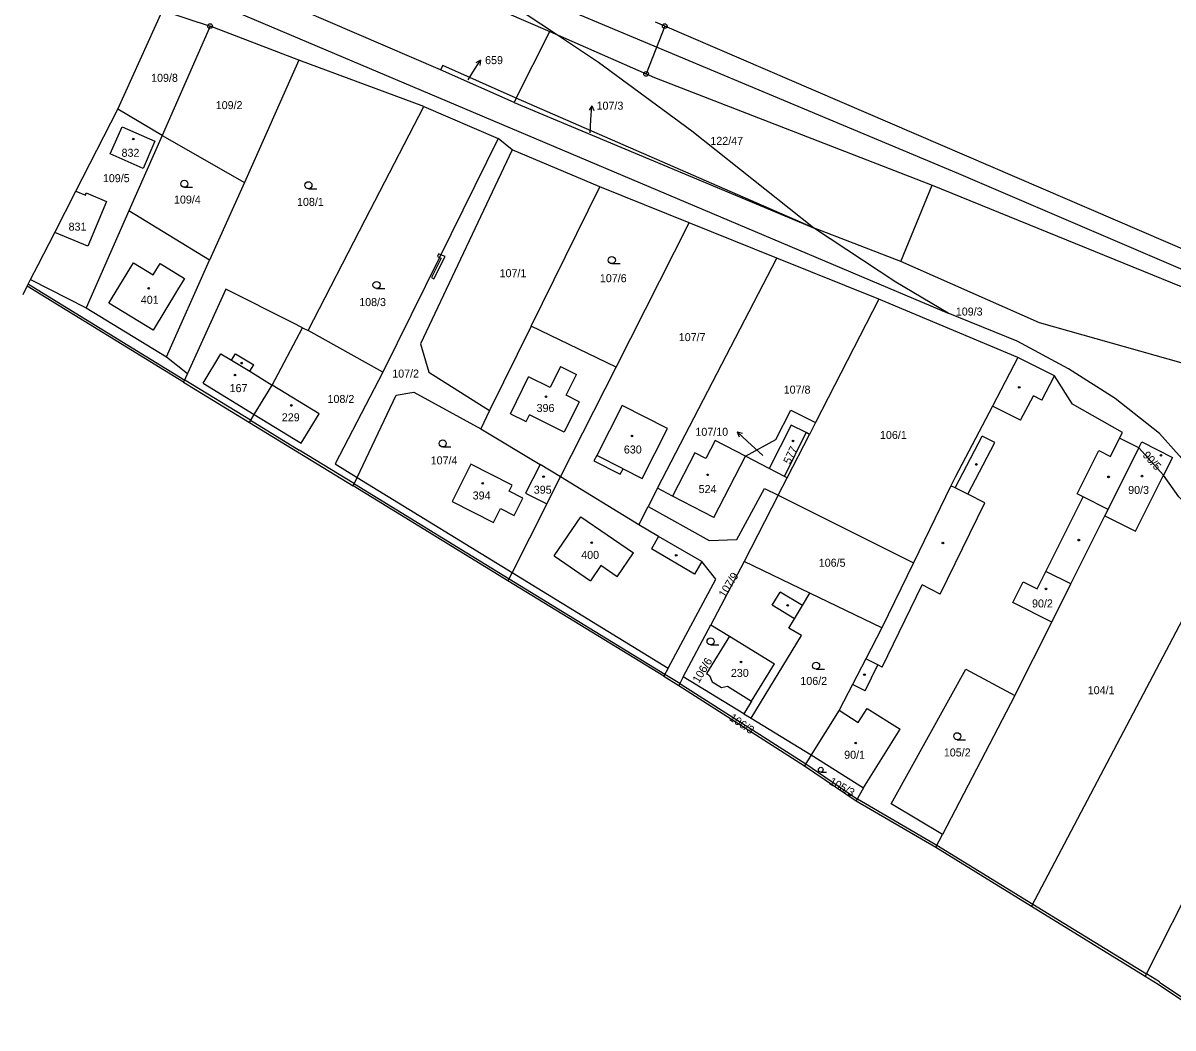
# Model space of a CAD drawing. Extents: x -783948 to -781889, y -1005870 to -1004430.
# Drawn here: x -783947.8 to -783703.5, y -1004871.2 to -1004657.7 of the extents above; entities that cross this region are included whole.
import ezdxf

# ---------------------------------------------------------------- set-up
doc = ezdxf.new("R2010")
doc.units = 0
for name, color, linetype in [('Vrstva 1', 7, 'Continuous'), ('Vrstva 13', 7, 'Continuous'), ('Vrstva 2', 7, 'Continuous'), ('Vrstva 3', 7, 'Continuous'), ('Vrstva 4', 7, 'Continuous'), ('Vrstva 5', 7, 'Continuous'), ('Vrstva 6', 7, 'Continuous'), ('Vrstva 7', 7, 'Continuous'), ('Vrstva 8', 7, 'Continuous')]:
    doc.layers.add(name, color=color, linetype=linetype)

msp = doc.modelspace()

# ---------------------------------------------------------------- linework, layer by layer
at = {"layer": 'Vrstva 1'}
for p, q in [((-783859.07, -1004667.69), (-783913.24, -1004644.21)), ((-783927.63, -1004676), (-783918.15, -1004655.06)), ((-783918.15, -1004655.06), (-783908.05, -1004658.37)), ((-783908.05, -1004658.37), (-783918.22, -1004681.57)), ((-783889.23, -1004665.59), (-783908.05, -1004658.37)), ((-783843.03, -1004673.66), (-783835.87, -1004659.49)), ((-783835.87, -1004659.49), (-783815.43, -1004668.52)), ((-783811.46, -1004658.38), (-783815.43, -1004668.52)), ((-783811.46, -1004658.38), (-783813.39, -1004657.55)), ((-783889.23, -1004665.59), (-783900.76, -1004691.57)), ((-783862.67, -1004675.47), (-783889.23, -1004665.59)), ((-783843.48, -1004674.57), (-783859.07, -1004667.69)), ((-783843.03, -1004673.66), (-783843.48, -1004674.57)), ((-783779.82, -1004701.19), (-783843.03, -1004673.66)), ((-783936.56, -1004693.41), (-783927.63, -1004676)), ((-783918.22, -1004681.57), (-783927.63, -1004676)), ((-783862.67, -1004675.47), (-783846.85, -1004682.27)), ((-783843.48, -1004674.57), (-783779.82, -1004701.19)), ((-783918.22, -1004681.57), (-783925.3, -1004697.6)), ((-783918.22, -1004681.57), (-783900.76, -1004691.57)), ((-783843.84, -1004684.65), (-783846.85, -1004682.27)), ((-783825.24, -1004692.52), (-783843.84, -1004684.65)), ((-783941.05, -1004702.18), (-783936.56, -1004693.41)), ((-783936.56, -1004693.41), (-783934.55, -1004694.26)), ((-783900.76, -1004691.57), (-783908.15, -1004708.1)), ((-783839.81, -1004722.07), (-783825.24, -1004692.52)), ((-783806.24, -1004700.16), (-783825.24, -1004692.52)), ((-783761.32, -1004708.36), (-783754.62, -1004692.14)), ((-783925.3, -1004697.6), (-783934.4, -1004718.22)), ((-783908.15, -1004708.1), (-783925.3, -1004697.6)), ((-783821.76, -1004730.78), (-783806.24, -1004700.16)), ((-783787.62, -1004707.64), (-783806.24, -1004700.16)), ((-783761.32, -1004708.36), (-783779.82, -1004701.19)), ((-783944.6, -1004709.09), (-783941.05, -1004702.18)), ((-783934.05, -1004705.1), (-783941.05, -1004702.18)), ((-783917.33, -1004728.64), (-783908.15, -1004708.1)), ((-783812.98, -1004756.53), (-783787.62, -1004707.64)), ((-783766, -1004716.39), (-783787.62, -1004707.64)), ((-783946.18, -1004712.18), (-783944.6, -1004709.09)), ((-783946.92, -1004713.62), (-783946.18, -1004712.18)), ((-783946.18, -1004712.18), (-783934.4, -1004718.22)), ((-783947.8, -1004715.34), (-783946.92, -1004713.62)), ((-783934.4, -1004718.22), (-783917.33, -1004728.64)), ((-783766, -1004716.39), (-783779.43, -1004742.59)), ((-783736.41, -1004728.73), (-783766, -1004716.39)), ((-783894.86, -1004734.6), (-783888.4, -1004722.45)), ((-783888.4, -1004722.45), (-783890.48, -1004721.4)), ((-783888.4, -1004722.45), (-783887.23, -1004723.03)), ((-783871.33, -1004731.87), (-783887.23, -1004723.03)), ((-783839.81, -1004722.07), (-783848.66, -1004740.03)), ((-783821.76, -1004730.78), (-783839.81, -1004722.07)), ((-783917.33, -1004728.64), (-783912.85, -1004732.15)), ((-783833.58, -1004754.1), (-783821.76, -1004730.78)), ((-783898.68, -1004740.83), (-783894.86, -1004734.6)), ((-783848.66, -1004740.03), (-783850.56, -1004743.9)), ((-783899.71, -1004742.52), (-783898.68, -1004740.83)), ((-783779.43, -1004742.59), (-783780.7, -1004745.07)), ((-783850.56, -1004743.9), (-783837.92, -1004751.49)), ((-783785.44, -1004754.31), (-783780.7, -1004745.07)), ((-783710.73, -1004747.93), (-783714.81, -1004745.89)), ((-783789.3, -1004752.31), (-783794.29, -1004749.72)), ((-783705.48, -1004753.77), (-783710.73, -1004747.93)), ((-783833.58, -1004754.1), (-783837.92, -1004751.49)), ((-783876.79, -1004754.24), (-783843.87, -1004774.4)), ((-783836.5, -1004759.86), (-783833.58, -1004754.1)), ((-783816.99, -1004764.26), (-783833.58, -1004754.1)), ((-783787.34, -1004758.01), (-783785.44, -1004754.31)), ((-783812.98, -1004756.53), (-783814.98, -1004760.38)), ((-783836.5, -1004759.86), (-783843.87, -1004774.4)), ((-783787.34, -1004758.01), (-783794.56, -1004772.1)), ((-783787.34, -1004758.01), (-783758.6, -1004772.33)), ((-783816.99, -1004764.26), (-783814.98, -1004760.38)), ((-783692.95, -1004768.16), (-783733.53, -1004845.25)), ((-783843.87, -1004774.4), (-783810.74, -1004794.7)), ((-783794.56, -1004772.1), (-783801.67, -1004785.52)), ((-783780.6, -1004778.83), (-783794.56, -1004772.1)), ((-783758.6, -1004772.33), (-783765.35, -1004786.19)), ((-783765.35, -1004786.19), (-783780.6, -1004778.83)), ((-783807.52, -1004796.54), (-783801.67, -1004785.52)), ((-783801.67, -1004785.52), (-783797.7, -1004787.95)), ((-783737.04, -1004800.55), (-783729.23, -1004784.93)), ((-783674.46, -1004791.02), (-783709.36, -1004860.11)), ((-783807.52, -1004796.54), (-783808.49, -1004798.38)), ((-783808.49, -1004798.38), (-783781.77, -1004815.48)), ((-783794.63, -1004804.42), (-783807.52, -1004796.54)), ((-783737.04, -1004800.55), (-783752.47, -1004830.07)), ((-783794.63, -1004804.42), (-783793.09, -1004805.36)), ((-783793.09, -1004805.36), (-783780.33, -1004813.16)), ((-783780.33, -1004813.16), (-783781.77, -1004815.48)), ((-783781.77, -1004815.48), (-783770.77, -1004822.93)), ((-783770.77, -1004822.93), (-783753.87, -1004832.75)), ((-783753.87, -1004832.75), (-783752.47, -1004830.07)), ((-783753.87, -1004832.75), (-783733.53, -1004845.25)), ((-783733.53, -1004845.25), (-783709.36, -1004860.11))]:
    msp.add_line(p, q, dxfattribs=at)
for points in [[(-783909.2, -1004634.42), (-783879.66, -1004642.5), (-783845.57, -1004655.35), (-783835.87, -1004659.49)], [(-783641.32, -1004731.39), (-783646.42, -1004729.36), (-783811.46, -1004658.38)], [(-783843.03, -1004673.66), (-783858.6, -1004666.75), (-783859.07, -1004667.69)], [(-783815.43, -1004668.52), (-783813.64, -1004669.31), (-783754.62, -1004692.14)], [(-783887.23, -1004723.03), (-783875.09, -1004699.51), (-783862.67, -1004675.47)], [(-783926.71, -1004679.77), (-783919.76, -1004682.83), (-783922.3, -1004688.59), (-783929.26, -1004685.51), (-783926.71, -1004679.77)], [(-783846.85, -1004682.27), (-783859.31, -1004707.52), (-783871.33, -1004731.87)], [(-783843.84, -1004684.65), (-783863.35, -1004725.85), (-783861.61, -1004731.84), (-783848.66, -1004740.03)], [(-783934.55, -1004694.26), (-783934.36, -1004693.8), (-783930.05, -1004695.61), (-783934.05, -1004705.1)], [(-783754.62, -1004692.14), (-783685.35, -1004720.33), (-783646.14, -1004738.05)], [(-783651.32, -1004749.59), (-783689.22, -1004733.41), (-783731.86, -1004721.38), (-783761.32, -1004708.36)], [(-783890.48, -1004721.4), (-783904.68, -1004714.23), (-783912.85, -1004732.15)], [(-783736.41, -1004728.73), (-783741.83, -1004739.06), (-783749.77, -1004754.2), (-783750.65, -1004756), (-783758.6, -1004772.33)], [(-783714.81, -1004745.89), (-783714.19, -1004744.65), (-783724.85, -1004738.66), (-783728.62, -1004732.62), (-783736.41, -1004728.73)], [(-783912.85, -1004732.15), (-783913.68, -1004733.97), (-783899.71, -1004742.52)], [(-783871.33, -1004731.87), (-783881.49, -1004751.36), (-783876.79, -1004754.24)], [(-783898.68, -1004740.83), (-783888.68, -1004746.96), (-783884.86, -1004740.73), (-783894.86, -1004734.6)], [(-783876.79, -1004754.24), (-783868.52, -1004736.77), (-783864.75, -1004736.11), (-783850.56, -1004743.9)], [(-783826.49, -1004750.71), (-783820.9, -1004753.54), (-783820.31, -1004752.37), (-783816.22, -1004754.45), (-783810.84, -1004743.84), (-783820.52, -1004738.93), (-783825.9, -1004749.54), (-783826.49, -1004750.71)], [(-783794.29, -1004749.72), (-783787.87, -1004746.14), (-783784.67, -1004739.9), (-783779.43, -1004742.59)], [(-783899.71, -1004742.52), (-783877.64, -1004756.04), (-783876.79, -1004754.24)], [(-783780.7, -1004745.07), (-783781.4, -1004744.71), (-783784.57, -1004743.09), (-783789.3, -1004752.31)], [(-783794.29, -1004749.72), (-783800.75, -1004746.37), (-783802.73, -1004750.19), (-783805.05, -1004748.99), (-783809.81, -1004758.17), (-783812.98, -1004756.53)], [(-783729.23, -1004784.93), (-783737.5, -1004780.79), (-783735.29, -1004776.37), (-783732.34, -1004777.85), (-783730.5, -1004774.17), (-783722.59, -1004758.35), (-783723.85, -1004757.72), (-783719.26, -1004748.53), (-783716.75, -1004749.78), (-783714.81, -1004745.89)], [(-783710.73, -1004747.93), (-783710.11, -1004746.69), (-783703.57, -1004749.96), (-783705.48, -1004753.77)], [(-783717.96, -1004762.38), (-783717.27, -1004761.01), (-783710.73, -1004747.93)], [(-783847.87, -1004763.77), (-783846.38, -1004760.82), (-783843.46, -1004762.3), (-783841.61, -1004758.65), (-783844.53, -1004757.17), (-783843.87, -1004755.87), (-783852.63, -1004751.43), (-783856.63, -1004759.34), (-783847.87, -1004763.77)], [(-783837.92, -1004751.49), (-783841.01, -1004757.57), (-783836.5, -1004759.86)], [(-783785.44, -1004754.31), (-783786.01, -1004754.02), (-783789.3, -1004752.31)], [(-783717.96, -1004762.38), (-783711.42, -1004765.65), (-783705.48, -1004753.77)], [(-783692.95, -1004768.16), (-783702.2, -1004758.31), (-783705.48, -1004753.77)], [(-783814.98, -1004760.38), (-783802.04, -1004767.62), (-783796.11, -1004767.41), (-783790.28, -1004756.54), (-783787.34, -1004758.01)], [(-783810.74, -1004794.7), (-783800.61, -1004775.8), (-783803.59, -1004772.11), (-783812.75, -1004766.74), (-783816.99, -1004764.26)], [(-783729.23, -1004784.93), (-783725.18, -1004776.83), (-783717.96, -1004762.38)], [(-783793.09, -1004805.36), (-783782.43, -1004787.8), (-783785.07, -1004786.2), (-783783.88, -1004784.24), (-783782.19, -1004781.45), (-783780.6, -1004778.83)], [(-783765.35, -1004786.19), (-783768.75, -1004792.75), (-783771.57, -1004798.18), (-783774.42, -1004803.68), (-783780.33, -1004813.16)], [(-783797.7, -1004787.95), (-783802.55, -1004795.89), (-783801.91, -1004796.28), (-783801.4, -1004797.65), (-783799.43, -1004798.85), (-783798.15, -1004798.58), (-783792.99, -1004801.73), (-783794.63, -1004804.42)], [(-783810.74, -1004794.7), (-783811.67, -1004796.44), (-783808.49, -1004798.38)], [(-783752.47, -1004830.07), (-783763.32, -1004823.54), (-783747.45, -1004794.95), (-783737.04, -1004800.55)], [(-783780.33, -1004813.16), (-783769.23, -1004820.15), (-783770.77, -1004822.93)], [(-783709.36, -1004860.11), (-783706.59, -1004861.81), (-783692.77, -1004871.15)]]:
    msp.add_lwpolyline(points, dxfattribs=at)
at = {"layer": 'Vrstva 13'}
for points in [[(-783861.04, -1004711.76), (-783860.51, -1004712.03), (-783858.14, -1004707.31), (-783859.03, -1004706.95), (-783859.31, -1004707.52), (-783858.96, -1004707.63)], [(-783859.52, -1004706.75), (-783859.75, -1004707.3), (-783859.31, -1004707.52), (-783859.03, -1004706.95)]]:
    msp.add_lwpolyline(points, close=True, dxfattribs=at)
at = {"layer": 'Vrstva 3'}
for p, q in [((-783913.51, -1004692.6), (-783911.76, -1004692.6)), ((-783887.15, -1004692.91), (-783885.4, -1004692.91)), ((-783822.7, -1004708.82), (-783820.95, -1004708.82)), ((-783872.69, -1004714.1), (-783870.94, -1004714.1)), ((-783858.62, -1004747.75), (-783856.87, -1004747.75)), ((-783801.72, -1004789.79), (-783799.97, -1004789.79)), ((-783779.29, -1004794.96), (-783777.54, -1004794.96)), ((-783749.3, -1004809.93), (-783747.55, -1004809.93)), ((-783778.3, -1004816.79), (-783777.12, -1004816.79))]:
    msp.add_line(p, q, dxfattribs=at)
for centre, radius in [((-783913.51, -1004691.85), 0.75), ((-783887.15, -1004692.16), 0.75), ((-783822.7, -1004708.07), 0.75), ((-783872.69, -1004713.35), 0.75), ((-783858.62, -1004747), 0.75), ((-783801.72, -1004789.04), 0.75), ((-783779.29, -1004794.21), 0.75), ((-783749.3, -1004809.18), 0.75), ((-783778.3, -1004816.29), 0.502)]:
    msp.add_circle(centre, radius, dxfattribs=at)
at = {"layer": 'Vrstva 4'}
for p, q in [((-783929.54, -1004717.18), (-783924.31, -1004708.66)), ((-783924.31, -1004708.66), (-783920.14, -1004711.2)), ((-783920.14, -1004711.2), (-783918.69, -1004708.82)), ((-783918.69, -1004708.82), (-783913.5, -1004712)), ((-783946.66, -1004713.19), (-783913.42, -1004733.54)), ((-783913.5, -1004712), (-783914.96, -1004714.38)), ((-783913.68, -1004733.97), (-783946.92, -1004713.62)), ((-783914.96, -1004714.38), (-783920.17, -1004722.91)), ((-783920.17, -1004722.91), (-783929.54, -1004717.18)), ((-783909.55, -1004734.17), (-783905.74, -1004727.94)), ((-783905.74, -1004727.94), (-783903.48, -1004729.33)), ((-783903.48, -1004729.33), (-783902.63, -1004727.94)), ((-783902.63, -1004727.94), (-783898.79, -1004730.29)), ((-783903.48, -1004729.33), (-783899.64, -1004731.68)), ((-783899.64, -1004731.68), (-783898.79, -1004730.29)), ((-783899.64, -1004731.68), (-783894.86, -1004734.6)), ((-783844.24, -1004740.68), (-783840.38, -1004732.85)), ((-783835.79, -1004735.11), (-783840.38, -1004732.85)), ((-783833.61, -1004730.68), (-783835.79, -1004735.11)), ((-783833.61, -1004730.68), (-783830.23, -1004732.34)), ((-783832.41, -1004736.77), (-783830.23, -1004732.34)), ((-783731.34, -1004737.8), (-783728.62, -1004732.62)), ((-783899.45, -1004742.09), (-783913.42, -1004733.54)), ((-783909.55, -1004734.17), (-783898.68, -1004740.83)), ((-783829.61, -1004738.15), (-783832.41, -1004736.77)), ((-783735.84, -1004742.06), (-783733.13, -1004736.9)), ((-783731.34, -1004737.8), (-783733.13, -1004736.9)), ((-783829.61, -1004738.15), (-783832.79, -1004744.61)), ((-783735.84, -1004742.06), (-783741.83, -1004739.06)), ((-783899.45, -1004742.09), (-783889.1, -1004748.43)), ((-783844.24, -1004740.68), (-783840.89, -1004742.33)), ((-783840.89, -1004742.33), (-783840.21, -1004740.95)), ((-783832.79, -1004744.61), (-783840.21, -1004740.95)), ((-783786.01, -1004754.02), (-783781.4, -1004744.71)), ((-783749.75, -1004756.45), (-783743.98, -1004745.44)), ((-783747.07, -1004757.79), (-783741.3, -1004746.78)), ((-783741.3, -1004746.78), (-783743.98, -1004745.44)), ((-783877.38, -1004755.61), (-783889.1, -1004748.43)), ((-783820.31, -1004752.37), (-783825.9, -1004749.54)), ((-783801.03, -1004762.72), (-783794.29, -1004749.72)), ((-783844.77, -1004776.17), (-783877.64, -1004756.04)), ((-783877.38, -1004755.61), (-783844.51, -1004775.74)), ((-783749.75, -1004756.45), (-783750.65, -1004756)), ((-783747.07, -1004757.79), (-783749.75, -1004756.45)), ((-783801.03, -1004762.72), (-783809.81, -1004758.17)), ((-783752.91, -1004778.99), (-783743.46, -1004759.59)), ((-783743.46, -1004759.59), (-783747.07, -1004757.79)), ((-783717.27, -1004761.01), (-783722.59, -1004758.35)), ((-783834.95, -1004770.85), (-783829.3, -1004762.59)), ((-783829.3, -1004762.59), (-783818.07, -1004770.27)), ((-783812.75, -1004766.74), (-783814.3, -1004769.38)), ((-783805.14, -1004774.75), (-783814.3, -1004769.38)), ((-783834.95, -1004770.85), (-783827.2, -1004776.15)), ((-783821.53, -1004775.32), (-783818.07, -1004770.27)), ((-783843.87, -1004774.4), (-783844.77, -1004776.17)), ((-783825.01, -1004772.94), (-783827.2, -1004776.15)), ((-783821.53, -1004775.32), (-783825.01, -1004772.94)), ((-783803.59, -1004772.11), (-783805.14, -1004774.75)), ((-783725.18, -1004776.83), (-783730.5, -1004774.17)), ((-783811.67, -1004796.44), (-783844.77, -1004776.17)), ((-783844.51, -1004775.74), (-783811.41, -1004796.01)), ((-783788.6, -1004781.37), (-783786.91, -1004778.58)), ((-783782.19, -1004781.45), (-783786.91, -1004778.58)), ((-783765.26, -1004794.5), (-783756.76, -1004777.06)), ((-783752.91, -1004778.99), (-783756.76, -1004777.06)), ((-783783.88, -1004784.24), (-783788.6, -1004781.37)), ((-783797.7, -1004787.95), (-783788.14, -1004793.79)), ((-783792.99, -1004801.73), (-783788.14, -1004793.79)), ((-783768.87, -1004799.53), (-783766.19, -1004794.03)), ((-783766.19, -1004794.03), (-783768.75, -1004792.75)), ((-783765.26, -1004794.5), (-783766.19, -1004794.03)), ((-783811.41, -1004796.01), (-783808.23, -1004797.95)), ((-783808.22, -1004797.96), (-783781.5, -1004815.06)), ((-783768.87, -1004799.53), (-783771.57, -1004798.18)), ((-783774.42, -1004803.68), (-783770.34, -1004806.25)), ((-783770.34, -1004806.25), (-783768.48, -1004803.27)), ((-783768.48, -1004803.27), (-783761.46, -1004807.7)), ((-783769.23, -1004820.15), (-783761.46, -1004807.7)), ((-783781.49, -1004815.07), (-783770.49, -1004822.52)), ((-783770.52, -1004822.5), (-783753.62, -1004832.32)), ((-783753.61, -1004832.32), (-783733.27, -1004844.82)), ((-783733.27, -1004844.82), (-783709.1, -1004859.68)), ((-783706.33, -1004861.38), (-783709.1, -1004859.68)), ((-783706.31, -1004861.4), (-783692.49, -1004870.74))]:
    msp.add_line(p, q, dxfattribs=at)
at = {"layer": 'Vrstva 5'}
for centre in [(-783924.36, -1004682.36), (-783921.1, -1004714.05), (-783901.34, -1004729.94), (-783902.76, -1004732.47), (-783736.15, -1004735.1), (-783836.69, -1004737.07), (-783890.79, -1004738.93), (-783818.42, -1004745.41), (-783784.21, -1004746.48), (-783706.01, -1004749.51), (-783745.25, -1004751.47), (-783837.21, -1004754.06), (-783802.35, -1004753.67), (-783717.16, -1004754.11), (-783710.06, -1004753.95), (-783850.13, -1004755.47), (-783826.97, -1004768.08), (-783752.36, -1004768.15), (-783723.49, -1004767.53), (-783809.01, -1004770.76), (-783730.44, -1004777.89), (-783785.32, -1004781.39), (-783795.27, -1004793.42), (-783769.03, -1004796.1), (-783770.88, -1004810.63)]:
    msp.add_circle(centre, 0.175, dxfattribs=at)
at = {"layer": 'Vrstva 6'}
for p, q in [((-783873.3, -1004637.56), (-783749.02, -1004689.7)), ((-783915.73, -1004649.72), (-783751.21, -1004719.35)), ((-783834.89, -1004659.85), (-783843.61, -1004654.14)), ((-783825.54, -1004666.07), (-783834.89, -1004659.85)), ((-783805.67, -1004680.66), (-783825.54, -1004666.07)), ((-783779.82, -1004701.19), (-783805.67, -1004680.66)), ((-783749.02, -1004689.7), (-783474.69, -1004807.3)), ((-783762.38, -1004712.77), (-783779.82, -1004701.19)), ((-783751.21, -1004719.35), (-783762.38, -1004712.77)), ((-783736.6, -1004725.25), (-783751.21, -1004719.35)), ((-783725.68, -1004731.15), (-783736.6, -1004725.25)), ((-783715.77, -1004737.49), (-783725.68, -1004731.15)), ((-783706.36, -1004744.89), (-783715.77, -1004737.49)), ((-783695.71, -1004756.85), (-783706.36, -1004744.89))]:
    msp.add_line(p, q, dxfattribs=at)
at = {"layer": 'Vrstva 7'}
for p, q in [((-783852.22, -1004668.13), (-783850.63, -1004665.58)), ((-783850.63, -1004665.58), (-783851.58, -1004666.17)), ((-783850.63, -1004665.58), (-783850.74, -1004666.7)), ((-783853.25, -1004669.77), (-783852.22, -1004668.13)), ((-783826.93, -1004675.27), (-783827.5, -1004676.23)), ((-783827.14, -1004678.26), (-783826.93, -1004675.27)), ((-783826.93, -1004675.27), (-783826.5, -1004676.3)), ((-783827.32, -1004681.07), (-783827.14, -1004678.26)), ((-783793.84, -1004746.57), (-783796.04, -1004744.52)), ((-783796.04, -1004744.52), (-783794.96, -1004744.84)), ((-783796.04, -1004744.52), (-783795.64, -1004745.57)), ((-783790.6, -1004749.57), (-783793.84, -1004746.57))]:
    msp.add_line(p, q, dxfattribs=at)
at = {"layer": 'Vrstva 8'}
for centre, radius in [((-783908.05, -1004658.37), 0.5), ((-783908.05, -1004658.37), 0.0303), ((-783811.46, -1004658.38), 0.5), ((-783811.46, -1004658.38), 0.0303), ((-783815.43, -1004668.52), 0.5), ((-783815.43, -1004668.52), 0.0303)]:
    msp.add_circle(centre, radius, dxfattribs=at)

# ---------------------------------------------------------------- texts
at = {"layer": 'Vrstva 2'}
for s, p in [('659', (-783849.62, -1004666.44)), ('109/8', (-783920.58, -1004670.2)), ('109/2', (-783906.85, -1004676)), ('107/3', (-783825.94, -1004676.12)), ('122/47', (-783801.76, -1004683.59)), ('832', (-783926.86, -1004686.12)), ('109/5', (-783930.83, -1004691.51)), ('109/4', (-783915.72, -1004696.06)), ('108/1', (-783889.58, -1004696.55)), ('831', (-783938.11, -1004701.81)), ('107/1', (-783846.54, -1004711.69)), ('107/6', (-783825.24, -1004712.76)), ('401', (-783922.77, -1004717.34)), ('108/3', (-783876.37, -1004717.83)), ('109/3', (-783749.61, -1004719.84)), ('107/7', (-783808.47, -1004725.27)), ('107/2', (-783869.35, -1004733.01)), ('167', (-783903.9, -1004736.11)), ('107/8', (-783786.18, -1004736.42)), ('108/2', (-783883.1, -1004738.4)), ('396', (-783838.68, -1004740.32)), ('229', (-783892.81, -1004742.3)), ('107/10', (-783804.94, -1004745.38)), ('106/1', (-783765.72, -1004746.05)), ('630', (-783820.14, -1004749.14)), ('107/4', (-783861.18, -1004751.45)), ('394', (-783852.26, -1004758.9)), ('395', (-783839.28, -1004757.68)), ('524', (-783804.25, -1004757.54)), ('90/3', (-783712.99, -1004757.73)), ('400', (-783829.2, -1004771.52)), ('106/5', (-783778.73, -1004773.19)), ('90/2', (-783733.42, -1004781.83)), ('230', (-783797.4, -1004796.59)), ('106/2', (-783782.64, -1004798.29)), ('104/1', (-783721.58, -1004800.26)), ('90/1', (-783773.33, -1004813.97)), ('105/2', (-783752.16, -1004813.48))]:
    msp.add_text(s, height=1.7, dxfattribs=at).set_placement(p)
for s, rotation, p in [('577', 65, (-783784.81, -1004751.54)), ('90/5', 312, (-783710.03, -1004749.59)), ('107/9', 58, (-783798.7, -1004779.9)), ('106/6', 59, (-783804.21, -1004798.04)), ('106/3', 326, (-783797.9, -1004805.64)), ('105/3', 331, (-783776.68, -1004819.3))]:
    msp.add_text(s, height=1.7, rotation=rotation, dxfattribs=at).set_placement(p)

doc.saveas('drawing.dxf')
